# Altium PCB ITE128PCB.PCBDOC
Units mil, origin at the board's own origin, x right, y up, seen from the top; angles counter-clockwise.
Board outline 1040 x 2455 mil, 2 copper layers (Top Layer, Bottom Layer); 5 components, 40 nets, 163 pads, 16 vias.
Unrouted connection lines stored in the file: 1.
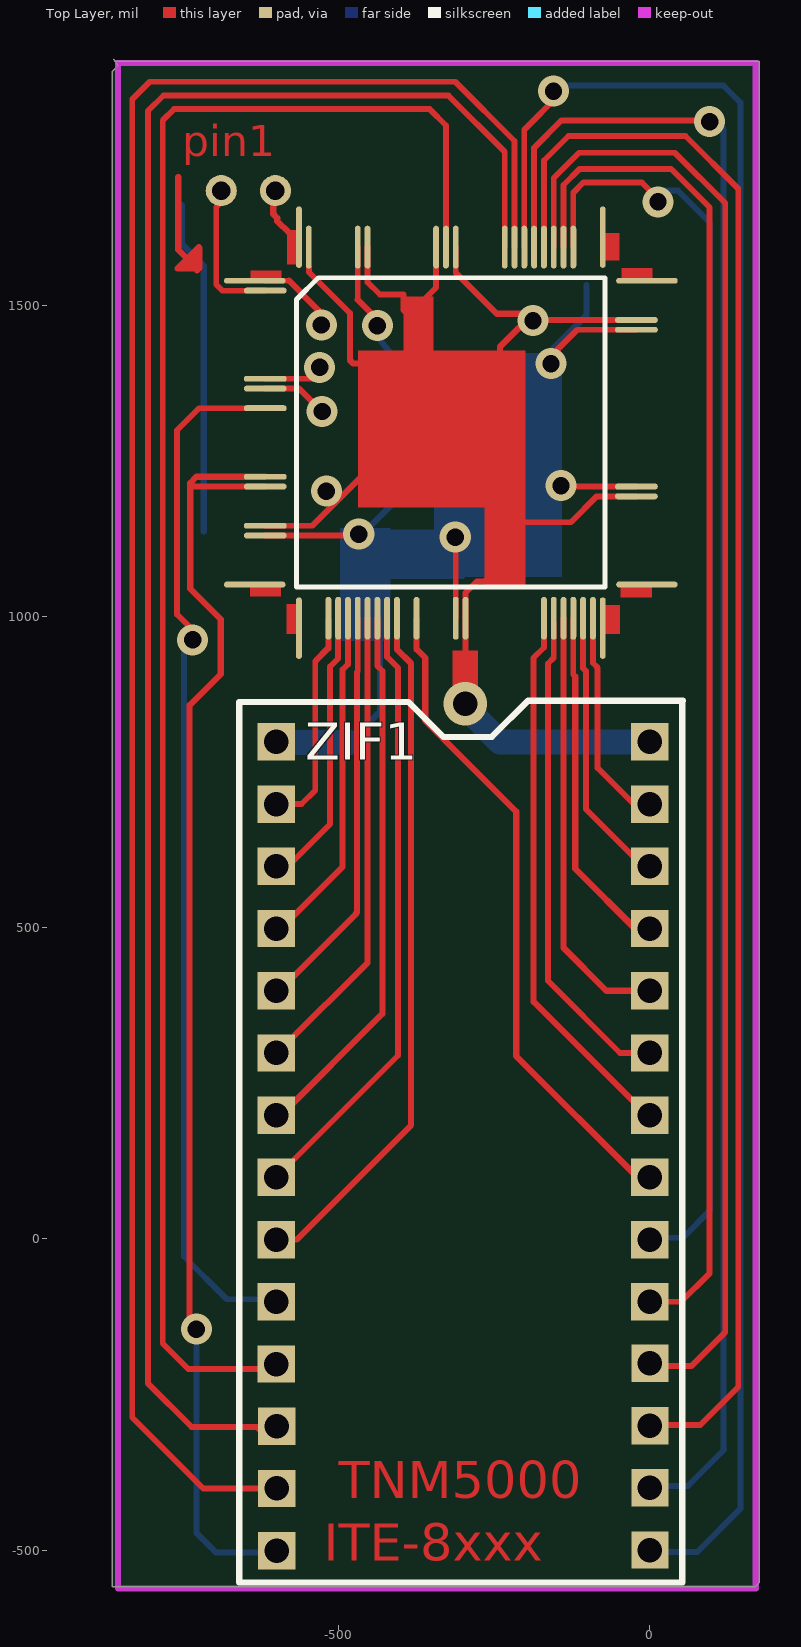
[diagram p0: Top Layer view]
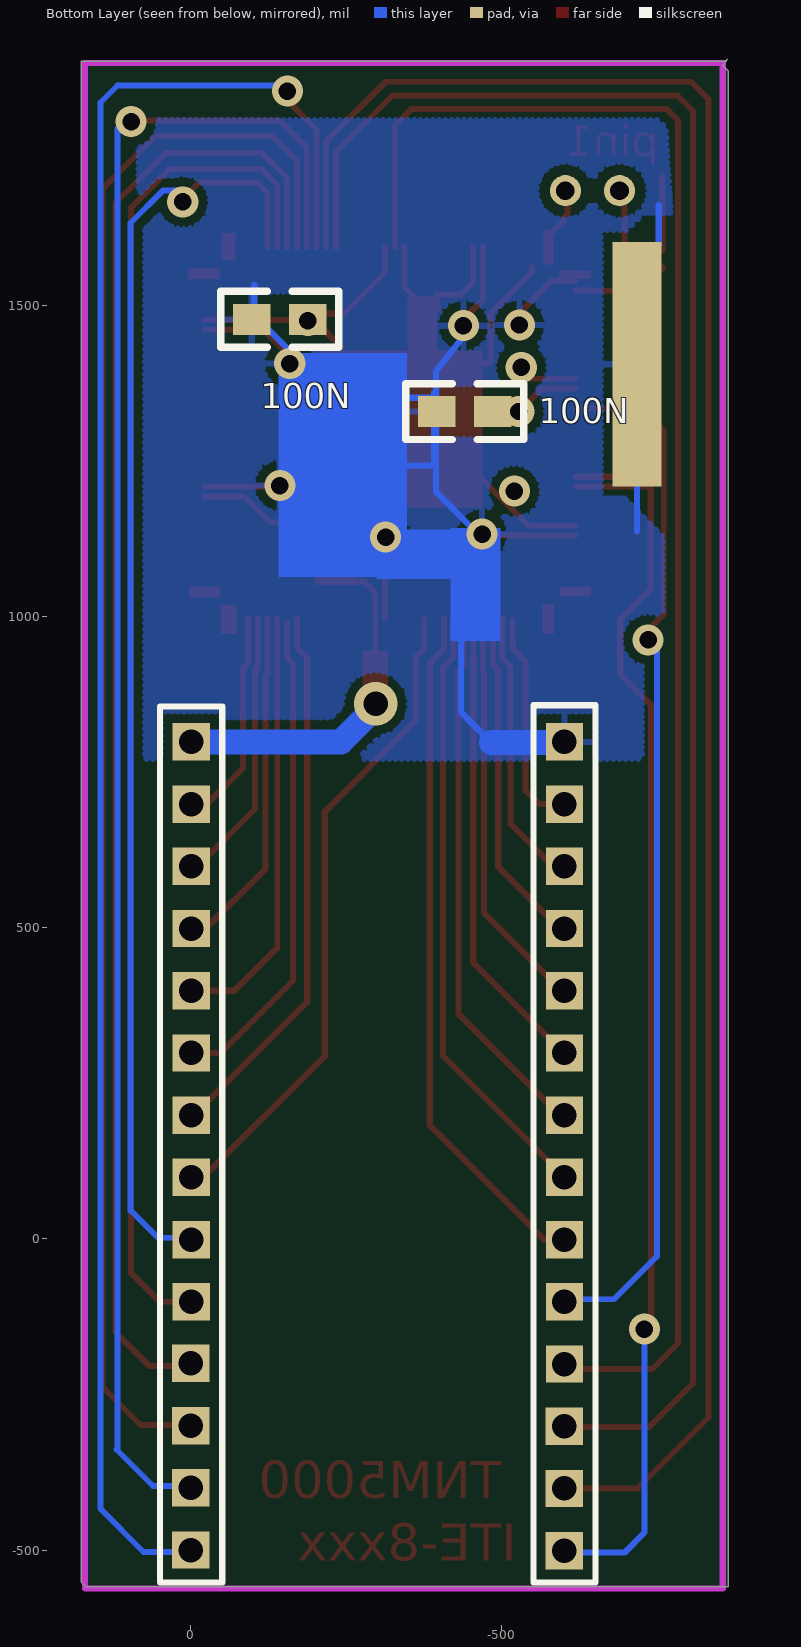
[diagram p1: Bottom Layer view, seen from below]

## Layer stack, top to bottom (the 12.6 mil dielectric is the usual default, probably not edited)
Top Layer: signal copper 1.4
Dielectric: dielectric 12.6, FR-4, Dk 4.8
Bottom Layer: signal copper 1.4

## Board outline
-862,1896 -859,1893 176,1893 176,-552 169,-559 -864,-559 -864,1877 -855,1886

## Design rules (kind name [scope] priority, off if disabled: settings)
Clearance [All] p1: gap=6
ComponentClearance [All] p1 off: gap=10 collisioncheckmode=3 verticalgap=10 showdistances=FALSE
Height [All] p1 off: minheight=0 maxheight=1000 prefheight=500
PolygonConnect [All] p1: connectstyle=Relief reliefconductorwidth=10 reliefentries=4 polygonreliefangle="90 Angle"
RoutingVias [All] p1: holewidth=28 width=50 viastyle="Through Hole" minholewidth=28 minwidth=50 maxholewidth=28 maxwidth=50
ShortCircuit [All] p1: allowed=TRUE
SilkscreenOverComponentPads [All] p1: minsilkscreentomaskgap=10
SolderMaskExpansion [All] p1: expansion=4
UnRoutedNet [All] p1 off:
Width [All] p1: maxlimit=40 minlimit=6 preferedwidth=9.4
23 further rules are at their usual default settings.

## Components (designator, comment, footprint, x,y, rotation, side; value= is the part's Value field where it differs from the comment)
100N "Comment" 0805 -485,1330 r0 bottom
100N "Comment" 0805 -188,1478 r0 bottom
? "10" "PCBComponent_1 - duplicate"#1 -0.52,898.99 r270 bottom
? "10" "PCBComponent_1 - duplicate"#2 -600.52,898.99 r270 bottom
? "Comment" TQFP128_N -320,1296 r0 top

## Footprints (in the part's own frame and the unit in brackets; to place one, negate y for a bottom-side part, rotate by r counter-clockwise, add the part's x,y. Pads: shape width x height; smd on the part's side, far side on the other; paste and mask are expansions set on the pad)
0805 [mil]
  rect 60x50 smd: 1(0,0) 2(90,0)
  silkscreen extent -50,-45 140,45
"PCBComponent_1 - duplicate"#1 [mil]
  rect 60x60 hole 39.37: 38(1098.99,-0.52) 39(1000,0) 40(900,0) 41(800,0) 42(700,0) 43(600,0) 44(500,0) 45(400,0) 46(300,0) 47(200,0) 48(100,0)
  silkscreen extent 43,-50 1451,50
"PCBComponent_1 - duplicate"#2 [mil]
  rect 60x60 hole 39.37: 1(100,0) 2(200,0) 3(300,0) 4(400,0) 5(500,0) 6(600,0) 7(700,0) 8(800,0) 9(900,0) 10(1000,0) 11(1100,0)
  silkscreen extent 41,-50 1451,50
TQFP128_N [mm] "Thin QFP, 128-Leads, Body 14x14mm, Pitch 0.4mm, IPC Medium Density"
  oval 2.512x0.24 smd: 1(-8.007,6.2) 32(-8.007,-6.2) 65(8.007,-6.2) 96(8.007,6.2)
  oval 1.75x0.24 smd: 2(-7.575,5.8) 11(-7.575,2.2) 12(-7.575,1.8) 14(-7.575,1) 21(-7.575,-1.8) 22(-7.575,-2.2) 26(-7.575,-3.8) 27(-7.575,-4.2) 74(7.575,-2.6) 75(7.575,-2.2) 91(7.575,4.2) 92(7.575,4.6)
  oval 1.75x0.24 on Top Overlay: 3(-7.575,5.4) 4(-7.575,5) 5(-7.575,4.6) 6(-7.575,4.2) 7(-7.575,3.8) 8(-7.575,3.4) 9(-7.575,3) 10(-7.575,2.6) 13(-7.575,1.4) 15(-7.575,0.6) 16(-7.575,0.2) 17(-7.575,-0.2) 18(-7.575,-0.6) 19(-7.575,-1) 20(-7.575,-1.4) 23(-7.575,-2.6) 24(-7.575,-3) 25(-7.575,-3.4) 28(-7.575,-4.6) 29(-7.575,-5) 30(-7.575,-5.4) 31(-7.575,-5.8) 66(7.575,-5.8) 67(7.575,-5.4) 68(7.575,-5) 69(7.575,-4.6) 70(7.575,-4.2) 71(7.575,-3.8) 72(7.575,-3.4) 73(7.575,-3) 76(7.575,-1.8) 77(7.575,-1.4) 78(7.575,-1) 79(7.575,-0.6) 80(7.575,-0.2) 81(7.575,0.2) 82(7.575,0.6) 83(7.575,1) 84(7.575,1.4) 85(7.575,1.8) 86(7.575,2.2) 87(7.575,2.6) 88(7.575,3) 89(7.575,3.4) 90(7.575,3.8) 93(7.575,5) 94(7.575,5.4) 95(7.575,5.8)
  oval 0.24x2.512 smd: 33(-6.2,-7.981) 64(6.2,-7.981) 97(6.2,7.981) 128(-6.2,7.981)
  oval 0.24x1.75 on Top Overlay: 34(-5.8,-7.575) 35(-5.4,-7.575) 44(-1.8,-7.575) 46(-1,-7.575) 47(-0.6,-7.575) 48(-0.2,-7.575) 51(1,-7.575) 52(1.4,-7.575) 53(1.8,-7.575) 54(2.2,-7.575) 55(2.6,-7.575) 56(3,-7.575) 57(3.4,-7.575) 98(5.8,7.575) 99(5.4,7.575) 108(1.8,7.575) 109(1.4,7.575) 110(1,7.575) 111(0.6,7.575) 115(-1,7.575) 116(-1.4,7.575) 117(-1.8,7.575) 118(-2.2,7.575) 119(-2.6,7.575) 120(-3,7.575) 123(-4.2,7.575) 124(-4.6,7.575) 125(-5,7.575) 126(-5.4,7.575)
  oval 0.24x1.75 smd: 36(-5,-7.575) 37(-4.6,-7.575) 38(-4.2,-7.575) 39(-3.8,-7.575) 40(-3.4,-7.575) 41(-3,-7.575) 42(-2.6,-7.575) 43(-2.2,-7.575) 45(-1.4,-7.575) 49(0.2,-7.575) 50(0.6,-7.575) 58(3.8,-7.575) 59(4.2,-7.575) 60(4.6,-7.575) 61(5,-7.575) 62(5.4,-7.575) 63(5.8,-7.575) 100(5,7.575) 101(4.6,7.575) 102(4.2,7.575) 103(3.8,7.575) 104(3.4,7.575) 105(3,7.575) 106(2.6,7.575) 107(2.2,7.575) 112(0.2,7.575) 113(-0.2,7.575) 114(-0.6,7.575) 121(-3.4,7.575) 122(-3.8,7.575) 127(-5.8,7.575)
  silkscreen extent -6.3,-6.3 6.3,6.32

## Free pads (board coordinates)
  round 50 hole 30: 0(-602,1685) 1(-689,1685)
  rect 78.74x393.7 smd far side: 2(-717,1406)
  rect 60x60 hole 39.37: 12(-600,-301) 13(-600,-401) 14(-600,-501) 35(0,-500) 36(0,-400) 37(0,-300)

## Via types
v1: diameter 50, hole 28, Top Layer to Bottom Layer, 15 vias
v2: diameter 70, hole 39.37, Top Layer to Bottom Layer, 1 vias

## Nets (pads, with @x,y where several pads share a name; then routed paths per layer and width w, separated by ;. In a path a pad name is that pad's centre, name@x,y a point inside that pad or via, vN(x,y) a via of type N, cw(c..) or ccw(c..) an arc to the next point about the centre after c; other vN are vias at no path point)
ACIN: 
AVCC: 
CE: ?.39@-0.52,-101.01 ?.101 | length 2208.2
  Top Layer w9.4: ?.101 -138.9,1632 -138.9,1694.1 -113,1720 34,1720 96,1658 96,-55 50,-101 ?.39@-9,-101
CLK1: ?.128 pad.0
CLK2: ?.2@-618.23,1524.35 pad.1 | length 242.6
  Top Layer w9.4: pad.1@-672,1684 -681,1675 -697,1659 -697,1534 -687,1524 ?.2@-646.67,1524 ; ?.2@-646,1524.35 ?.2@-618.23,1524.35
CLKPCI: 
FLASHEN: ?.40@-0.52,-1.01 ?.100 | length 2033.1
  Top Layer w9.4: ?.100 -123.15,1681.85 -107,1698 -13,1698 3,1682 v1@6,1685
  Bottom Layer w9.4: v1@6,1685 45,1685 97,1633 97,892 97,46 53,2 ?.40@13,2
  other v1: 13,1667
GND: 100N.2 ?.1 ?.27 ?.49 ?.75 ?.91 ?.122 pad.2 | length 2794.6
  Top Layer w9.4: ?.27 v1@-486.65,1130.65 ; ?.1@-618.23,1540.09 -580.09,1540.09 ; -469.61,1509.61 ?.122 ; ?.49 v1@-312.13,1115.87 ; v1@-160,1418 -116.65,1461.35 ?.91 ; v1@-132.61,1209.39 ?.75
  Top Layer w10: -580.09,1540.09 -532,1492 v1@-532,1464 ; -469.61,1509.61 v1@-447,1487
  Bottom Layer w10: -752,1662 -752,1599 -717,1564 pad.2 -717,1137 ; -483,798 -433.96,847.04 -433.96,1101.96 ; v1@-461,1140 -455,1140 -393.96,1201.04 -393.96,1360.21 -393.96,1394.96 -444,1458 v1@-444,1485 ; -390.96,1360.21 -390.96,1243.21 -347.21,1243.21 -309,1205 v1@-145,1205 ; 100N.2@-385,1352 -343,1352 ; v1@-164,1423 -101.96,1485.04 -101.96,1533.21 ; v1@-160,1217 -160,1305
  Bottom Layer w40: ?.1@-608,798 -483,798
  other v1: -313,1128 -468,1133 -143,1211 -159,1407 -438,1468 -528,1469
GP0: ?.106 pad.13 | length 3234.1
  Top Layer w9.4: pad.13 -718,-401 -832,-287 -832,1832 -804,1860 -313,1860 -217.64,1764.64 ?.106
GP1: ?.107 pad.12 | length 3054.8
  Top Layer w9.4: pad.12@-610,-324 -632,-302 -737,-302 -807,-232 -807,1813 -782,1838 -324,1838 -233.39,1747.39 ?.107
GP6: ?.104 pad.36 | length 2754
  Top Layer w9.4: ?.104 -186.14,1753.86 -142,1798 99,1798 v1@105.5,1791.5
  Bottom Layer w9.4: pad.36@-14,-397 61,-397 119.5,-338.5 ; 118,-339 v1@118,1785
  other v1: 96,1796
KSI0: ?.42@-0.52,198.99 ?.58 | length 878.2
  Top Layer w9.4: -187,934 -170.39,950.61 ?.58
  Top Layer w10: -187,934 -187,381 ?.42@-7,201
KSI1: ?.43@-0.52,298.99 ?.59 | length 790.4
  Top Layer w9.4: ?.59@-154.69,990 -154.69,934.31 -164,925 -164,415 -47.99,298.99 ?.43@-0.52,298.99
KSI2: ?.44@-0.52,398.99 ?.60 | length 701.3
  Top Layer w9.4: -138.9,467.9 ?.60
  Top Layer w10: -138.9,467.9 -70,399 ?.44@4,399
KSI3: ?.45@-0.52,498.99 ?.61 | length 545.5
  Top Layer w9.4: ?.61 -123.15,907.15 -120,904
  Top Layer w10: -120,904 -120,595 ?.45@-20,495
KSI4: ?.46@-0.52,598.99 ?.62 | length 431.6
  Top Layer w9.4: ?.62 -107.4,917.4 -103,913 -103,691 ?.46@-16,604
KSI5: ?.47@-0.52,698.99 ?.63 | length 347.8
  Top Layer w9.4: ?.63 -91.65,925.65 -84,918 -84,757 -24,697 ?.47@-5,697
KSO0: ?.2@-600.52,698.99 ?.36 | length 383.7
  Top Layer w9.4: ?.2@-600.52,698.99 -560.01,698.99 -538,721 -538,929 -516.85,950.15 ; -537,929 -516.85,949.15 -516.85,950.15 ; ?.36@-516.85,994.85 -516.85,950.15
KSO1: ?.3@-600.52,598.99 ?.37 | length 438.9
  Top Layer w9.4: ?.3@-589,600 -581,600 -514,667 -514,920 -501.1,932.9 -501.1,942 ?.37
KSO2: ?.4@-600.52,498.99 ?.38@-485.35,997.77 | length 544.8
  Top Layer w9.4: -494,915 -485.35,923.65 ?.38@-485.35,997.77
  Top Layer w10: ?.4@-594,498 -494,598 -494,915
KSO3: ?.5@-600.52,398.99 ?.39@-469.61,997.77 | length 644.1
  Top Layer w9.4: -472,524 -471,525 -471,911 -469.61,912.39 ?.39@-469.61,997.77
  Top Layer w10: ?.5@-591,404 -472,523 -472,524
KSO4: ?.6@-600.52,298.99 ?.40@-453.86,997.77 | length 743.5
  Top Layer w9.4: -453.86,936.05 ?.40@-453.86,997.77
  Top Layer w10: ?.6@-586,312 -453.86,444.14 -453.86,936.05 -453.86,939
KSO5: ?.7@-600.52,198.99 ?.41@-438.11,997.77 | length 869.6
  Top Layer w9.4: ?.41@-438.11,997.77 -438.11,921.11 -430,913
  Top Layer w10: ?.7@-593,199 -430,362 -430,913
KSO6: ?.8@-600.52,98.99 ?.42@-422.36,997.77 | length 964.5
  Top Layer w9.4: ?.8@-585,115 -405,295 -405,918 -422.36,935.36 ?.42@-422.36,997.77
KSO7: ?.9@-600.52,-1.01 ?.43@-406.61,997.77 | length 1119.9
  Top Layer w9.4: -406.61,947.61 ?.43@-406.61,997.77
  Top Layer w10: ?.9@-600.52,-1.01 -568.01,-1.01 -384,183 -384,339 ; -406.61,947.61 -384,925 -384,339 ; -384,336 -384,339
KSO8: 
KSO9: ?.41@-0.52,98.99 ?.45@-375.12,997.77 | length 1063.4
  Top Layer w9.4: -375.09,948.09 ?.45@-375.09,996
  Top Layer w10: -375,948 -361,934 -361,833 -215,687 -215,294 -19.99,98.99 ?.41@-0.52,98.99
LIDON: 
NOVO: 
POWE: 
RST1: ?.21 ?.22 pad.14 | length 2122.2
  Top Layer w10: -735.61,1209.39 ?.22 ; v1(-729,-145) -740,-134 -740,858 -690,908 -690,996 -739,1045 -739,1215 -728.87,1225.13 ?.21
  Bottom Layer w10: v1(-729,-145) -729,-472 -697,-504 pad.14@-595,-504
RST3: 
RSTW: ?.10@-600.52,-101.01 ?.14 | length 1673.7
  Top Layer w9.4: v1@-751,971 -739,983 -760,1004 -760,1300 -724.63,1335.37 ?.14
  Bottom Layer w9.4: v1@-749,958 -749,-28 -680,-97 ?.10@-589,-97
  other v1: -735,963
SDI: ?.38@0,-200 ?.102 | length 2412.5
  Top Layer w9.4: ?.102 -154.65,1705.35 -114,1746 40,1746 121,1665 121,-150 67,-204 ?.38@-17,-204
SDO: ?.103 pad.37 | length 2596
  Top Layer w9.4: ?.103 -170.39,1733.61 -131,1773 57,1773 142,1688 142,-238 81,-299 26,-299 pad.37@8,-317
SELGND: ?.11@-600.52,-201.01 ?.113 | length 2837
  Top Layer w9.4: ?.11@-598,-209 -742,-209 -783,-168 -783,1798 -765,1816 -354,1816 -327.87,1789.87 ?.113
SPICLK: ?.105 pad.35 | length 3010.7
  Top Layer w9.4: ?.105 -201.89,1783.11 v1@-146,1839
  Bottom Layer w9.4: v1(-155,1845) -146,1854 118,1854 145.4,1826.6 145.4,-433.6 76,-503 pad.35@7,-503
VCC: ?.11@-618.23,1382.61 | length 82.8
  Top Layer w9.4: ?.11@-618.23,1382.61 v1@-535.39,1382.61
  other v1: -531,1401
VCORE: 100N.1@-485,1330 ?.12 | length 106.5
  Top Layer w9.4: ?.12 -563.87,1366.87
  Top Layer w10: -563.87,1366.87 v1(-527,1330)
VSB: 100N.1@-188,1478 ?.26 ?.48@-0.52,798.99 ?.50 ?.74 ?.92 ?.112 ?.114 ?.121 ?.127 | length 2733.4
  Top Layer w9.4: ?.26 -542.61,1146.39 -464,1225 ; ?.127@-548,1562 -548,1554 -482,1488 ; ?.121 -453.86,1537.86 -434,1518 ; -368,1505 -343.62,1529.38 ?.114 ; ?.112 -312.13,1553.13 -246,1487 ; v2@-296.38,866.62 ?.50 -296.38,1038.62 -278,1057 -266,1057 -254.84,1068.16 -254.84,1094.16 -241,1108 ; -211,1152 -127,1152 -85.36,1193.64 ?.74 ; v1@-197.9,1477.1 ?.92
  Top Layer w10: -482,1488 -482,1412 -477,1407 -244,1407 -241,1410 ; -464,1225 -285,1225 -241,1181 ; -434,1518 -396.43,1518 -396.21,1518.21 -396.21,1493.21 -377,1474 -376,1474 -376,1468 -368,1468 ; -368,1462 -368,1468 ; -368,1505 -368,1468 ; -246,1487 v1@-195,1487 ; -241,1108 -241,1181 ; v1@-197.9,1477.1 -241,1434 -241,1410 ; -241,1181 -241,1410
  Bottom Layer w40: v2@-301,859 -240.99,798.99 ?.48@-0.52,798.99
  other v1: -520,1202 -188,1476
  other v2: -297,860
pads on no net: ?.3@-618.23,1508.6 ?.4@-618.23,1492.85 ?.5@-618.23,1477.1 ?.6@-618.23,1461.35 ?.7@-618.23,1445.61 ?.8@-618.23,1429.86 ?.9@-618.23,1414.11 ?.10@-618.23,1398.36 ?.13 ?.15 ?.16 ?.17 ?.18 ?.19 ?.20 ?.23 ?.24 ?.25 ?.28 ?.29 ?.30 ?.31 ?.32 ?.33 ?.34 ?.35 ?.44@-390.87,997.77 ?.46@-359.37,997.77 ?.47@-343.62,997.77 ?.48@-327.87,997.77 ?.51 ?.52 ?.53 ?.54 ?.55 ?.56 ?.57 ?.64 ?.65 ?.66 ?.67 ?.68 ?.69 ?.70 ?.71 ?.72 ?.73 ?.76 ?.77 ?.78 ?.79 ?.80 ?.81 ?.82 ?.83 ?.84 ?.85 ?.86 ?.87 ?.88 ?.89 ?.90 ?.93 ?.94 ?.95 ?.96 ?.97 ?.98 ?.99 ?.108 ?.109 ?.110 ?.111 ?.115 ?.116 ?.117 ?.118 ?.119 ?.120 ?.123 ?.124 ?.125 ?.126
copper on no net: | length 308.5
  Top Layer w10: -758,1707 -758,1590 -744.5,1576.5 ; -728,1557 -725,1560 -759,1560 -725,1594 ; -724,1561 -724,1593 ; -605.5,1660.5 -605.5,1647.5 -599,1641 -599,1636 -580,1617

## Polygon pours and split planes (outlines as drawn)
GND on Bottom Layer "Top Layer-No Net 1" (hatched 90Degree grid 10 track 10, remove dead copper, pour order 1000): -771,1649 -728,1649 -724,1645 -684,1605 -684,1576 -684,1203 -722,1165 -758,1129 -758,1054 -758,764 -748,754 -730,772 84,772 84,1782 92,1790 84,1798 -740,1798 -751,1798 -763,1786

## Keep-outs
Keep-Out Layer:
  lines w10: -855,-562 -855,1890 170,1890 170,-562 -855,-562

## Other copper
Top Layer:
  rectangle: -47,1031 3,1049
  rectangle: -46,1543 4,1561
  rectangle net GND: -642,1543 -592,1557
  region net CLK1: -567,1566 -567,1622 -583,1622 -583,1566
  region: -49,1573 -49,1617 -72,1617 -72,1573
  region: -48,972 -48,1019 -73,1019 -73,972
  region: -565,972 -565,1021 -584,1021 -584,972
  rectangle: -643,1033 -593,1048
  rectangle net VSB: -396,1392 -348,1515
  rectangle net VSB: -469,1176 -200,1428
  rectangle net VSB: -317,860 -276,946
  rectangle net VSB: -266,1051 -200,1203
  rectangle: -741,1557 -728,1585
  rectangle: -754,1556 -736,1572
  text "pin1" at -752,1740 h50
  text "TNM5000" at -500,-417 h60
  text "ITE-8xxx" at -524,-517 h60
Bottom Layer:
  rectangle net GND: -498,961 -417,1143
  rectangle net GND: -345,1143 -286,1309
  rectangle net GND: -347,1064 -141,1424
  rectangle net GND: -436,1061 -298,1140

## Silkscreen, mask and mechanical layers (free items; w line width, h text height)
Top Overlay:
  lines w10: 52,864 52,-552 -660,-552 -660,863 -388,863 -332,807 -254,807 -196,865 53,865
  text "ZIF1" at -554,770 h60
Top Solder:
  rectangle: -583,946 -565,1024
  rectangle: -672,1034 -592,1052
  rectangle: -674,1542 -593,1556
  rectangle: -578,1561 -567,1650
  rectangle: -72,1569 -57,1648
  rectangle: -51,1543 28,1557
  rectangle: -53,1035 32,1049
  rectangle: -74,936 -68,1023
